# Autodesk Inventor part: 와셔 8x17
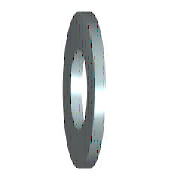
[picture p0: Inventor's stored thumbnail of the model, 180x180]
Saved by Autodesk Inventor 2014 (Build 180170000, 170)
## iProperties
IsCustomPart: 1
Created: 2012-02
Part Number: 와셔 8x17
Material: 강철, 연강
Description: 평면 와셔
Document SubType Name: Modeling
Standard: KS B 1326
Designer: mduedu
Standards Organization: KS
Language: ko-KR
Size Designation: 8x17
Categories: <MemberInstance><Categories><Category DisplayName="조임쇠" InternalName="e4da775c-781d-43d5-af7c-5136215cf5a6" Mnemonic="FSTN"><Category DisplayName="와셔" InternalN
Density: 1 g/cm^3
Appearance: 노란색
Author: mduedu
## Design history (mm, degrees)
sketch "스케치"
  geometry: C1 r 8.5 at (0, 0); C2 r 4.2 at (0, 0); 1 further point
  constraints: 2 centre point, 2 coincident
  dimensions: "d0" = 8.4 diameter of C2 (= SD1); "d1" = 17 diameter of C1 (= SD2)
extrude "본체" new body sketch "스케치" distance "d2" = 1.6 (= SD); taper "d3" = 0 deg
workaxis "Work Axis1"
workplane "Work Plane1"
body "Solid1"
other parameters: "SD1" = 8.4 [user parameter; used in 1 equation term], "SD2" = 17 [user parameter; used in 1 equation term], "SD" = 1.6 [user parameter; used in 1 equation term], "d4" = 0, "d5" = 0, "d6" = 0, "d7" = 0, "NND" = 8 [user parameter]
